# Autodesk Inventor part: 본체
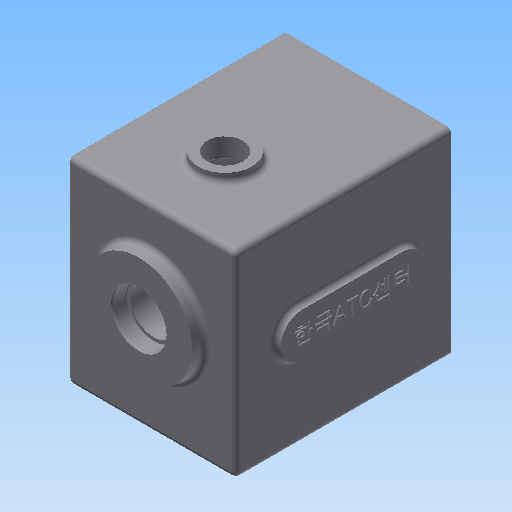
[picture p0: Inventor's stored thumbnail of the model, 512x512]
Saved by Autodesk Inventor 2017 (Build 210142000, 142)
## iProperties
Created: 2016-02
Part Number: 본체
Material: 일반
Document SubType Name: Modeling
Designer: mduedu
Density: 1 g/cm^3
Appearance: 기본값
Author: mduedu
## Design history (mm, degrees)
sketch "스케치1"
  geometry: L1 (-47, -47)-(47, -47); L2 (47, -47)-(47, 63); L3 (47, 63)-(-47, 63); L4 (-47, 63)-(-47, -47); 2 further points
  constraints: 8 end point, 2 parallel, 1 horizontal, 1 midpoint, 1 perpendicular, 1 vertical alignment
  dimensions: "d0" = 94 distance of L2.end L3.end; "d155" = 110 distance of L1.end L2.end; "d156" = 47 distance from line of L1 point (0, 0)
extrude "돌출1" new body sketch "스케치1" distance "d2" = 120; taper "d3" = 0 deg
sketch "스케치3"
  geometry: L1 (47, -47)-(-47, -47) reference; L2 (47, 63)-(47, -47) reference; L3 (-47, 63)-(47, 63) reference; L4 (-47, -47)-(-47, 63) reference; L5 (37, 53)-(37, -37); L6 (37, -37)-(-37, -37); L7 (-37, -37)-(-37, 53); L8 (-37, 53)-(37, 53); 1 further point
  constraints: 8 end point, 3 other
  dimensions: "d226" = 10 distance between parallel lines of L8 L3
extrude "돌출3" cut sketch "스케치3" distance "d11" = 110; taper "d12" = 0 deg
sketch "스케치4"
  geometry: C1 r 21 at (0, 11); 1 further point
  constraints: 1 centre point, 1 vertical alignment
  dimensions: "d13" = 21 radius of C1; "d227" = 11 distance of point (0, 0) C1.centre
extrude "돌출4" join sketch "스케치4" distance "d16" = 7; taper "d17" = 0 deg
sketch "스케치5"
  geometry: C1 r 15 at (0, -20); 1 further point
  constraints: 1 centre point, 1 vertical alignment
  dimensions: "d18" = 15 radius of C1; "d20" = 20 distance of point (0, 0) C1.centre
extrude "돌출5" join sketch "스케치5" distance "d21" = 7; taper "d22" = 0 deg
sketch "스케치6"
  geometry: C1 r 30 at (0, 11); A1 r 21 centre (0, 11) between (8.978, -7.984) and (-8.978, -7.984) reference; 1 further point
  constraints: 1 centre point, 1 coincident
  dimensions: "d228" = 60 diameter of C1
extrude "돌출6" join sketch "스케치6" distance "d25" = 7; taper "d26" = -3 deg
hole "구멍1" diameter "d29" = 30; stored, may be unused: countersink angle "d33" = 90 deg, drill point angle "d35" = 0 deg; dims "d30" = 6, "d31" = 4, "d32" = 2, "d34" = 7, "d269" = 10, "d270" = 10
hole "구멍2" diameter "d38" = 22; stored, may be unused: countersink angle "d42" = 90 deg, drill point angle "d44" = 0 deg; dims "d36" = 10, "d37" = 10, "d39" = 6, "d40" = 4, "d41" = 2, "d43" = 7
hole "구멍3" diameter "d47" = 19; stored, may be unused: countersink angle "d51" = 90 deg, drill point angle "d53" = 0 deg; dims "d45" = 10, "d46" = 10, "d48" = 6, "d49" = 4, "d50" = 2, "d52" = 1
hole "구멍4" diameter "d56" = 30; stored, may be unused: countersink angle "d60" = 90 deg, drill point angle "d62" = 0 deg; dims "d57" = 6, "d58" = 4, "d59" = 2, "d61" = 8.3, "d271" = 10, "d272" = 10
hole "구멍5" diameter "d65" = 26; stored, may be unused: countersink angle "d69" = 90 deg, drill point angle "d71" = 0 deg; dims "d66" = 6, "d67" = 4, "d68" = 2, "d70" = 8, "d267" = 10, "d268" = 10
fillet "모깎기2" dims "d73" = 0.3
fillet "모깎기3" dims "d74" = 2
chamfer "모따기1" distance "d75" = 1; stored, may be unused: second distance "d76" = 2, angle "d77" = 45 deg
fillet "모깎기4" dims "d78" = 3
fillet "모깎기23" dims "d240" = 1
fillet "모깎기20" dims "d229" = 3
sketch "스케치23"
  geometry: L1 (-37, 53)-(37, 53) reference; L2 (37, 53)-(37, -37) reference; L3 (37, -37)-(-37, -37) reference; L4 (-37, -37)-(-37, 53) reference; L5 (44, -47)-(-44, -47) reference; L6 (47, 60)-(47, -44) reference; L7 (-44, 63)-(44, 63) reference; L8 (-47, -44)-(-47, 60) reference; C1 r 10 at (-37, 53); C2 r 10 at (37, 53); C3 r 10 at (-37, -37); C4 r 10 at (37, -37); A1 r 3 centre (-44, -44) between (-47, -44) and (-44, -47) reference; A2 r 3 centre (44, -44) between (44, -47) and (47, -44) reference; A3 r 3 centre (44, 60) between (47, 60) and (44, 63) reference; A4 r 3 centre (-44, 60) between (-44, 63) and (-47, 60) reference; 1 further point
  constraints: 4 centre point, 4 coincident, 3 equal radius
  dimensions: "d230" = 20 diameter of C1
extrude "돌출22" join sketch "스케치23" stored distance "d235" = 10; taper "d236" = 0 deg
fillet "모깎기21" dims "d237" = 3
node "작업 평면1"
fillet "모깎기22" dims "d239" = 1
sketch "스케치12"
  geometry: A1 r 10 centre (-37, 53) between (-34.692, 43.27) and (-27.27, 50.692) reference; A2 r 10 centre (37, 53) between (27.27, 50.692) and (34.692, 43.27) reference; A3 r 10 centre (37, -37) between (34.692, -27.27) and (27.27, -34.692) reference; A4 r 10 centre (-37, -37) between (-27.27, -34.692) and (-34.692, -27.27) reference; 5 further points
  constraints: 4 coincident
hole "구멍6" sketch "스케치12" at (-37, 53), (37, 53), (37, -37), (-37, -37) diameter "d122" = 3.242; stored, may be unused: countersink angle "d126" = 90 deg, drill point angle "d128" = 120 deg; dims "d123" = 7, "d124" = 4, "d125" = 2, "d127" = 9
sketch "스케치20"
  geometry: L1 (44, 0)-(-44, 0) reference; L2 (44, -120)-(-44, -120) reference; L3 (0, 0)-(0, -120); L4 (-44, -120)-(-44, 0) reference; L5 (44, 0)-(44, -120) reference; C1 r 10 at (0, -79)
  constraints: 2 end point, 1 centre point, 1 midpoint, 1 point on line
  dimensions: "d189" = 20 diameter of C1; "d190" = 41 distance from line of C1.centre L2
extrude "돌출19" cut sketch "스케치20" stored distance "d191" = 10; taper "d192" = 0 deg
sketch "스케치18"
  geometry: C1 r 15 at (0, -79); C2 r 10 at (0, -79) reference; 1 further point
  constraints: 1 centre point, 1 concentric
  dimensions: "d174" = 30 diameter of C1
extrude "돌출17" join sketch "스케치18" distance "d175" = 5; taper "d176" = 0 deg
fillet "모깎기16" dims "d177" = 3
sketch "스케치19"
  geometry: C1 r 15 at (24.351, 79); C2 r 10 at (24.351, 79) reference; 1 further point
  constraints: 1 centre point, 1 concentric
  dimensions: "d178" = 30 diameter of C1
extrude "돌출18" cut sketch "스케치19" distance "d181" = 5; taper "d182" = 0 deg
chamfer "모따기5" distance "d183" = 1; stored, may be unused: second distance "d184" = 2, angle "d185" = 45 deg
fillet "모깎기24" dims "d242" = 3, "d243" = 3
sketch "스케치24"
  geometry: L1 (-86, 64)-(-30, 64); L2 (-30, 64)-(-30, 40); L3 (-30, 40)-(-86, 40); L4 (-86, 40)-(-86, 64); L5 (0, 0)-(0, 104) reference; L6 (-86, 52)-(-30, 52); L7 (-58, 64)-(-58, 40); A1 r 12 centre (-86, 52) between (-86, 40) and (-86, 64); A2 r 12 centre (-30, 52) between (-30, 64) and (-30, 40); A3 r 12 centre (-30, 52) between (-30, 40) and (-30, 64); A4 r 12 centre (-86, 52) between (-86, 64) and (-86, 40); 2 further points
  constraints: 12 end point, 8 point on circle, 5 midpoint, 4 centre point, 2 parallel, 2 perpendicular, 1 horizontal, 1 horizontal alignment
  dimensions: "d244" = 58 distance between parallel lines of L7 L5; "d245" = 80 dimension on A2 A1; "d246" = 24 distance between parallel lines of L3 L1
extrude "돌출23" join sketch "스케치24" distance "d247" = 3; taper "d248" = 0 deg
fillet "모깎기25" dims "d249" = 3
sketch "스케치25"
  geometry: L1 (-30, 64)-(-86, 64) reference; L2 (-86, 40)-(-30, 40) reference; A1 r 12 centre (-86, 52) between (-86, 64) and (-86, 40) reference; A2 r 12 centre (-30, 52) between (-30, 40) and (-30, 64) reference; 3 further points
  constraints: 1 horizontal alignment, 1 midpoint, 1 vertical alignment, 1 other
feature "엠보싱3" sketch "스케치25" dims "d32" = 2, "d250" = 0.5, "d251" = 0
sketch "스케치26"
  geometry: L1 (14.367, 127)-(73.633, 127) reference; L2 (0, 0)-(88, 0) reference; L3 (88, 120)-(0, 120) reference; 5 further points
  constraints: 3 vertical alignment, 2 midpoint
  dimensions: "d252" = 35 distance from line of point (44, 35) L2; "d253" = 35 distance from line of point (44, 85) L3; "d254" = 50 distance of point (44, 35) point (44, 85) (derived)
hole "구멍8" sketch "스케치26" at (44, 85), (44, 35) diameter "d255" = 6.647; stored, may be unused: countersink angle "d259" = 90 deg, drill point angle "d261" = 118 deg; dims "d256" = 6, "d257" = 4, "d258" = 2, "d260" = 8
chamfer "모따기7" distance "d262" = 0.8; stored, may be unused: second distance "d263" = 2, angle "d264" = 30 deg
node "솔리드1"
node "투영된 루프1"
node "투영된 루프4"
node "투영된 루프5"
node "투영된 루프6"
